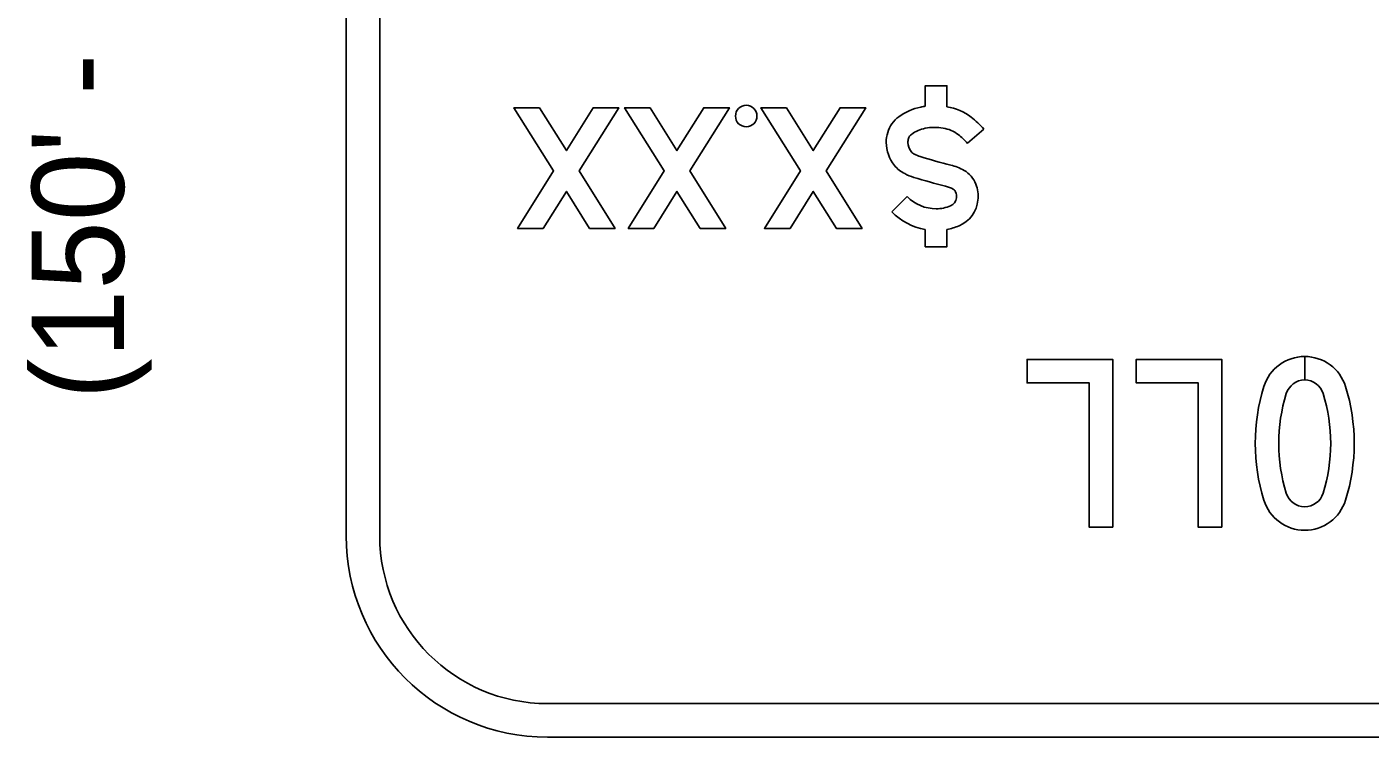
# Model space of a CAD drawing. Extents: x -102643 to -98250, y 54554 to 62384.
# Drawn here: x -102643 to -102142, y 56625 to 56890 of the extents above; entities that cross this region are included whole.
import ezdxf

# ---------------------------------------------------------------- set-up
doc = ezdxf.new("R2010")
doc.units = 0
for name, color, linetype in [('GSBWFill', 7, 'Continuous'), ('GSColorFill', 7, 'Continuous'), ('GSOutline', 7, 'Continuous'), ('SignPanel', 7, 'Continuous'), ('SignPanel_ep', 7, 'Continuous'), ('TextLabel', 7, 'Continuous')]:
    doc.layers.add(name, color=color, linetype=linetype)

msp = doc.modelspace()

# ---------------------------------------------------------------- linework, layer by layer
at = {"layer": 'GSBWFill'}
for p, q in [((-102166.86, 56758.44), (-102166.86, 56767.19)), ((-102166.86, 56767.19), (-102166.86, 56758.44))]:
    msp.add_line(p, q, dxfattribs=at)
for points in [[(-102308.27, 56860.37), (-102308.27, 56868.03), (-102300.18, 56868.03), (-102300.18, 56860.2)], [(-102286.42, 56851.85), (-102292.54, 56846.57)], [(-102320.74, 56821.07), (-102314.97, 56826.73)], [(-102300.18, 56814.47), (-102300.18, 56808.05), (-102308.27, 56808.05), (-102308.27, 56814.47)]]:
    msp.add_lwpolyline(points, dxfattribs=at)
for points in [[(-102238.42, 56703.6), (-102247.17, 56703.6), (-102247.17, 56757.35), (-102270.3, 56757.35), (-102270.3, 56766.1), (-102238.42, 56766.1)], [(-102197.8, 56703.6), (-102206.55, 56703.6), (-102206.55, 56757.35), (-102229.67, 56757.35), (-102229.67, 56766.1), (-102197.8, 56766.1)]]:
    msp.add_lwpolyline(points, close=True, dxfattribs=at)
for centre, radius, start, end in [((-102305.62, 56839.24), 21.29, 101.6446, 126.0677), ((-102304.95, 56835.99), 24.61, 97.7484, 101.6446), ((-102303.59, 56839.93), 20.56, 52.6492, 80.4549), ((-102311.61, 56847.46), 11.12, 126.0677, 163.4972), ((-102310.1, 56831.4), 31.29, 40.8202, 52.6492), ((-102309.7, 56846.9), 13.11, 163.4972, 180), ((-102309.7, 56846.9), 5.03, 163.4972, 180), ((-102311.61, 56847.46), 3.03, 126.0677, 163.4972), ((-102305.62, 56839.24), 13.21, 101.6446, 126.0677), ((-102304.95, 56835.99), 16.52, 90, 101.6446), ((-102304.95, 56831.6), 20.92, 80.7349, 90), ((-102303.59, 56839.93), 12.47, 52.6492, 80.7349), ((-102310.1, 56831.4), 23.2, 40.8202, 52.6492), ((-102309.37, 56846.9), 13.44, 180, 219.5561), ((-102309.37, 56846.9), 5.35, 180, 219.5561), ((-102310.49, 56845.97), 3.9, 219.5561, 243.0108), ((-102310.49, 56845.97), 11.99, 219.5561, 243.0108), ((-102306.15, 56854.5), 13.48, 243.0108, 252.8961), ((-102248.36, 57042.31), 209.97, 252.8961, 256.1067), ((-102303.43, 56819.67), 19.37, 60.1812, 76.1067), ((-102306.15, 56854.5), 21.56, 243.0108, 252.8961), ((-102248.36, 57042.31), 218.06, 252.8961, 256.1067), ((-102298.79, 56827.77), 10.04, 21.2247, 60.1812), ((-102303.43, 56819.67), 11.29, 60.1812, 76.1067), ((-102298.79, 56827.77), 1.96, 21.2247, 60.1812), ((-102301.39, 56826.75), 4.76, 354.1421, 21.2247), ((-102301.39, 56826.75), 12.84, 354.1421, 21.2247), ((-102304.15, 56837.35), 15.16, 224.4342, 270), ((-102304.15, 56835.56), 13.37, 270, 293.3248), ((-102300.3, 56826.64), 3.66, 293.3248, 354.1421), ((-102300.3, 56826.64), 11.75, 293.3248, 354.1421), ((-102304.15, 56837.35), 23.24, 224.4342, 259.7866), ((-102304.15, 56835.56), 21.45, 280.65, 293.3248), ((-102166.86, 56751.26), 15.94, 90.0112, 162.6717), ((-102166.86, 56751.26), 15.94, 17.3283, 90), ((-102166.86, 56751.26), 7.19, 90.0249, 162.6717), ((-102166.86, 56751.26), 7.19, 17.3283, 90), ((-102114.28, 56734.85), 71.02, 162.6717, 197.3283), ((-102114.28, 56734.85), 62.27, 162.6717, 197.3283), ((-102219.44, 56734.85), 62.27, 342.6717, 17.3283), ((-102219.44, 56734.85), 71.02, 342.6717, 17.3283), ((-102166.86, 56718.44), 15.94, 197.3283, 342.6717), ((-102166.86, 56718.44), 7.19, 197.3283, 342.6717)]:
    msp.add_arc(centre, radius, start, end, dxfattribs=at)
at = {"layer": 'GSColorFill'}
for p, q in [((-102166.86, 56758.44), (-102166.86, 56767.19)), ((-102166.86, 56767.19), (-102166.86, 56758.44))]:
    msp.add_line(p, q, dxfattribs=at)
for points in [[(-102308.27, 56860.37), (-102308.27, 56868.03), (-102300.18, 56868.03), (-102300.18, 56860.2)], [(-102286.42, 56851.85), (-102292.54, 56846.57)], [(-102320.74, 56821.07), (-102314.97, 56826.73)], [(-102300.18, 56814.47), (-102300.18, 56808.05), (-102308.27, 56808.05), (-102308.27, 56814.47)]]:
    msp.add_lwpolyline(points, dxfattribs=at)
for points in [[(-102238.42, 56703.6), (-102247.17, 56703.6), (-102247.17, 56757.35), (-102270.3, 56757.35), (-102270.3, 56766.1), (-102238.42, 56766.1)], [(-102197.8, 56703.6), (-102206.55, 56703.6), (-102206.55, 56757.35), (-102229.67, 56757.35), (-102229.67, 56766.1), (-102197.8, 56766.1)]]:
    msp.add_lwpolyline(points, close=True, dxfattribs=at)
for centre, radius, start, end in [((-102305.62, 56839.24), 21.29, 101.6446, 126.0677), ((-102304.95, 56835.99), 24.61, 97.7484, 101.6446), ((-102303.59, 56839.93), 20.56, 52.6492, 80.4549), ((-102311.61, 56847.46), 11.12, 126.0677, 163.4972), ((-102310.1, 56831.4), 31.29, 40.8202, 52.6492), ((-102309.7, 56846.9), 13.11, 163.4972, 180), ((-102309.7, 56846.9), 5.03, 163.4972, 180), ((-102311.61, 56847.46), 3.03, 126.0677, 163.4972), ((-102305.62, 56839.24), 13.21, 101.6446, 126.0677), ((-102304.95, 56835.99), 16.52, 90, 101.6446), ((-102304.95, 56831.6), 20.92, 80.7349, 90), ((-102303.59, 56839.93), 12.47, 52.6492, 80.7349), ((-102310.1, 56831.4), 23.2, 40.8202, 52.6492), ((-102309.37, 56846.9), 13.44, 180, 219.5561), ((-102309.37, 56846.9), 5.35, 180, 219.5561), ((-102310.49, 56845.97), 3.9, 219.5561, 243.0108), ((-102310.49, 56845.97), 11.99, 219.5561, 243.0108), ((-102306.15, 56854.5), 13.48, 243.0108, 252.8961), ((-102248.36, 57042.31), 209.97, 252.8961, 256.1067), ((-102303.43, 56819.67), 19.37, 60.1812, 76.1067), ((-102306.15, 56854.5), 21.56, 243.0108, 252.8961), ((-102248.36, 57042.31), 218.06, 252.8961, 256.1067), ((-102298.79, 56827.77), 10.04, 21.2247, 60.1812), ((-102303.43, 56819.67), 11.29, 60.1812, 76.1067), ((-102298.79, 56827.77), 1.96, 21.2247, 60.1812), ((-102301.39, 56826.75), 4.76, 354.1421, 21.2247), ((-102301.39, 56826.75), 12.84, 354.1421, 21.2247), ((-102304.15, 56837.35), 15.16, 224.4342, 270), ((-102304.15, 56835.56), 13.37, 270, 293.3248), ((-102300.3, 56826.64), 3.66, 293.3248, 354.1421), ((-102300.3, 56826.64), 11.75, 293.3248, 354.1421), ((-102304.15, 56837.35), 23.24, 224.4342, 259.7866), ((-102304.15, 56835.56), 21.45, 280.65, 293.3248), ((-102166.86, 56751.26), 15.94, 90.0112, 162.6717), ((-102166.86, 56751.26), 15.94, 17.3283, 90), ((-102166.86, 56751.26), 7.19, 90.0249, 162.6717), ((-102166.86, 56751.26), 7.19, 17.3283, 90), ((-102114.28, 56734.85), 71.02, 162.6717, 197.3283), ((-102114.28, 56734.85), 62.27, 162.6717, 197.3283), ((-102219.44, 56734.85), 62.27, 342.6717, 17.3283), ((-102219.44, 56734.85), 71.02, 342.6717, 17.3283), ((-102166.86, 56718.44), 15.94, 197.3283, 342.6717), ((-102166.86, 56718.44), 7.19, 197.3283, 342.6717)]:
    msp.add_arc(centre, radius, start, end, dxfattribs=at)
at = {"layer": 'GSOutline'}
for points in [[(-102308.27, 56860.37), (-102308.27, 56868.03), (-102300.18, 56868.03), (-102300.18, 56860.2)], [(-102286.42, 56851.85), (-102292.54, 56846.57)], [(-102320.74, 56821.07), (-102314.97, 56826.73)], [(-102300.18, 56814.47), (-102300.18, 56808.05), (-102308.27, 56808.05), (-102308.27, 56814.47)]]:
    msp.add_lwpolyline(points, dxfattribs=at)
for points in [[(-102238.42, 56703.6), (-102247.17, 56703.6), (-102247.17, 56757.35), (-102270.3, 56757.35), (-102270.3, 56766.1), (-102238.42, 56766.1)], [(-102197.8, 56703.6), (-102206.55, 56703.6), (-102206.55, 56757.35), (-102229.67, 56757.35), (-102229.67, 56766.1), (-102197.8, 56766.1)]]:
    msp.add_lwpolyline(points, close=True, dxfattribs=at)
for centre, radius, start, end in [((-102305.62, 56839.24), 21.29, 101.6446, 126.0677), ((-102304.95, 56835.99), 24.61, 97.7484, 101.6446), ((-102303.59, 56839.93), 20.56, 52.6492, 80.4549), ((-102311.61, 56847.46), 11.12, 126.0677, 163.4972), ((-102310.1, 56831.4), 31.29, 40.8202, 52.6492), ((-102309.7, 56846.9), 13.11, 163.4972, 180), ((-102309.7, 56846.9), 5.03, 163.4972, 180), ((-102311.61, 56847.46), 3.03, 126.0677, 163.4972), ((-102305.62, 56839.24), 13.21, 101.6446, 126.0677), ((-102304.95, 56835.99), 16.52, 90, 101.6446), ((-102304.95, 56831.6), 20.92, 80.7349, 90), ((-102303.59, 56839.93), 12.47, 52.6492, 80.7349), ((-102310.1, 56831.4), 23.2, 40.8202, 52.6492), ((-102309.37, 56846.9), 13.44, 180, 219.5561), ((-102309.37, 56846.9), 5.35, 180, 219.5561), ((-102310.49, 56845.97), 3.9, 219.5561, 243.0108), ((-102310.49, 56845.97), 11.99, 219.5561, 243.0108), ((-102306.15, 56854.5), 13.48, 243.0108, 252.8961), ((-102248.36, 57042.31), 209.97, 252.8961, 256.1067), ((-102303.43, 56819.67), 19.37, 60.1812, 76.1067), ((-102306.15, 56854.5), 21.56, 243.0108, 252.8961), ((-102248.36, 57042.31), 218.06, 252.8961, 256.1067), ((-102298.79, 56827.77), 10.04, 21.2247, 60.1812), ((-102303.43, 56819.67), 11.29, 60.1812, 76.1067), ((-102298.79, 56827.77), 1.96, 21.2247, 60.1812), ((-102301.39, 56826.75), 4.76, 354.1421, 21.2247), ((-102301.39, 56826.75), 12.84, 354.1421, 21.2247), ((-102304.15, 56837.35), 15.16, 224.4342, 270), ((-102304.15, 56835.56), 13.37, 270, 293.3248), ((-102300.3, 56826.64), 3.66, 293.3248, 354.1421), ((-102300.3, 56826.64), 11.75, 293.3248, 354.1421), ((-102304.15, 56837.35), 23.24, 224.4342, 259.7866), ((-102304.15, 56835.56), 21.45, 280.65, 293.3248), ((-102166.86, 56751.26), 15.94, 17.3283, 162.6717), ((-102166.86, 56751.26), 7.19, 17.3283, 162.6717), ((-102114.28, 56734.85), 71.02, 162.6717, 197.3283), ((-102114.28, 56734.85), 62.27, 162.6717, 197.3283), ((-102219.44, 56734.85), 62.27, 342.6717, 17.3283), ((-102219.44, 56734.85), 71.02, 342.6717, 17.3283), ((-102166.86, 56718.44), 15.94, 197.3283, 342.6717), ((-102166.86, 56718.44), 7.19, 197.3283, 342.6717)]:
    msp.add_arc(centre, radius, start, end, dxfattribs=at)
at = {"layer": 'SignPanel'}
for points in [[(-102452, 56859.81), (-102442.01, 56843.88), (-102432.01, 56859.81), (-102422.47, 56859.81), (-102437.24, 56836.28), (-102423.82, 56814.89), (-102433.36, 56814.89), (-102442.01, 56828.67), (-102450.66, 56814.89), (-102460.2, 56814.89), (-102446.78, 56836.28), (-102461.55, 56859.81)], [(-102452, 56859.81), (-102442.01, 56843.88), (-102432.01, 56859.81), (-102422.47, 56859.81), (-102437.24, 56836.28), (-102423.82, 56814.89), (-102433.36, 56814.89), (-102442.01, 56828.67), (-102450.66, 56814.89), (-102460.2, 56814.89), (-102446.78, 56836.28), (-102461.55, 56859.81)], [(-102452, 56859.81), (-102442.01, 56843.88), (-102432.01, 56859.81), (-102422.47, 56859.81), (-102437.24, 56836.28), (-102423.82, 56814.89), (-102433.36, 56814.89), (-102442.01, 56828.67), (-102450.66, 56814.89), (-102460.2, 56814.89), (-102446.78, 56836.28), (-102461.55, 56859.81)], [(-102410.77, 56859.81), (-102400.78, 56843.88), (-102390.78, 56859.81), (-102381.24, 56859.81), (-102396.01, 56836.28), (-102382.59, 56814.89), (-102392.13, 56814.89), (-102400.78, 56828.67), (-102409.43, 56814.89), (-102418.97, 56814.89), (-102405.55, 56836.28), (-102420.32, 56859.81)], [(-102410.77, 56859.81), (-102400.78, 56843.88), (-102390.78, 56859.81), (-102381.24, 56859.81), (-102396.01, 56836.28), (-102382.59, 56814.89), (-102392.13, 56814.89), (-102400.78, 56828.67), (-102409.43, 56814.89), (-102418.97, 56814.89), (-102405.55, 56836.28), (-102420.32, 56859.81)], [(-102410.77, 56859.81), (-102400.78, 56843.88), (-102390.78, 56859.81), (-102381.24, 56859.81), (-102396.01, 56836.28), (-102382.59, 56814.89), (-102392.13, 56814.89), (-102400.78, 56828.67), (-102409.43, 56814.89), (-102418.97, 56814.89), (-102405.55, 56836.28), (-102420.32, 56859.81)], [(-102359.99, 56859.81), (-102349.99, 56843.88), (-102340, 56859.81), (-102330.45, 56859.81), (-102345.22, 56836.28), (-102331.8, 56814.89), (-102341.34, 56814.89), (-102349.99, 56828.67), (-102358.64, 56814.89), (-102368.18, 56814.89), (-102354.76, 56836.28), (-102369.53, 56859.81)], [(-102359.99, 56859.81), (-102349.99, 56843.88), (-102340, 56859.81), (-102330.45, 56859.81), (-102345.22, 56836.28), (-102331.8, 56814.89), (-102341.34, 56814.89), (-102349.99, 56828.67), (-102358.64, 56814.89), (-102368.18, 56814.89), (-102354.76, 56836.28), (-102369.53, 56859.81)], [(-102359.99, 56859.81), (-102349.99, 56843.88), (-102340, 56859.81), (-102330.45, 56859.81), (-102345.22, 56836.28), (-102331.8, 56814.89), (-102341.34, 56814.89), (-102349.99, 56828.67), (-102358.64, 56814.89), (-102368.18, 56814.89), (-102354.76, 56836.28), (-102369.53, 56859.81)]]:
    msp.add_lwpolyline(points, close=True, dxfattribs=at)
msp.add_ellipse((-102374.98, 56856.72), major_axis=(0, -4), ratio=0.99997, dxfattribs=at)
msp.add_ellipse((-102374.98, 56856.72), major_axis=(0, -4), ratio=0.99997, dxfattribs=at)
msp.add_ellipse((-102374.98, 56856.72), major_axis=(0, -4), ratio=0.99997, dxfattribs=at)
at = {"layer": 'SignPanel_ep'}
for p, q in [((-102524.05, 57112.97), (-102524.05, 56700.47)), ((-102524.05, 57112.97), (-102524.05, 56700.47)), ((-102511.55, 56700.47), (-102511.55, 57112.97)), ((-102511.55, 56700.47), (-102511.55, 57112.97)), ((-101699.05, 56637.97), (-102449.05, 56637.97)), ((-101699.05, 56637.97), (-102449.05, 56637.97)), ((-102449.05, 56625.47), (-101699.05, 56625.47)), ((-102449.05, 56625.47), (-101699.05, 56625.47))]:
    msp.add_line(p, q, dxfattribs=at)
for radius in [75, 75, 62.5, 62.5]:
    msp.add_arc((-102449.05, 56700.47), radius, 180, 270, dxfattribs=at)

# ---------------------------------------------------------------- texts
at = {"layer": 'TextLabel'}
msp.add_text("(150' - 300')", height=34.335, rotation=90, dxfattribs=at).set_placement((-102606.88, 56751.21))

doc.saveas('drawing.dxf')
